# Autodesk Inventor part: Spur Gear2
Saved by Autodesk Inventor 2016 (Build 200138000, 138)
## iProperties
Created: 2016-10
Part Number: Spur Gear2
Material: Steel
Document SubType Name: Modeling
Designer: Ingenieria
Categories: <?xml version="1.0" encoding="UTF-16"?> <MemberInstance><Categories><FamilyTemplate><FamilyTemplateParameter ValueType="xs:double" Id="1" ObjectReferenceKey="da
Density: 1 g/cm^3
Appearance: Steel
CustomPartVersion: 1
Author: Ingenieria
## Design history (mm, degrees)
sketch "Sketch1"
  geometry: C1 r 266.187 at (0, 0)
  constraints: 1 centre point
  dimensions: "d0" = 532.37337 diameter of C1 (= da_da)
extrude "Extrusion1" new body sketch "Sketch1" distance "d1" = 60 (= da_b); taper "d2" = 0 deg
workplane "Work Plane2"
sketch "Sketch2"
  geometry: C1 r 266.187 at (0, 0) reference; C2 r 261.193 at (0, 0)
  constraints: 1 centre point, 1 coincident
  dimensions: "d3" = 522.38588 diameter of C2 (= da_dw)
feature "Pitch Diameter" sketch "Sketch2" dims "d4" = 10, "d5" = 0
workplane "Work Plane8"
workplane "Work Plane9"
feature "Spur Gear" dims "d5" = 0, "da_b" = 60, "da_d" = 520, "da_aw" = 341.56, "da_da" = 532.37337, "da_df" = 509.92655, "da_dw" = 522.38588, angle "da_beta" = 0 deg, "da_lefttooth" = 0, "da_righttooth" = 0
body "Solid1"
body "Srf1"
other parameters: "d16" = 341.56 (= da_aw), "d17" = 0, "d34" = 0.30208 (computed from da_z), "d39" = 0, "d41" = 0, "d43" = 341.56 (= da_aw), "d46" = 341.56 (= da_aw), "d47" = 0, "d48" = 0
